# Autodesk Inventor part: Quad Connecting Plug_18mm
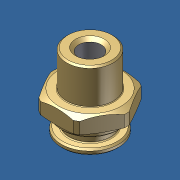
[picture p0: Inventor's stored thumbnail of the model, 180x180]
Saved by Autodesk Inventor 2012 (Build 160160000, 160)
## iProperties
Created: 2013-10
Part Number: Quad Connecting Plug_18mm
Material: Default
Document SubType Name: Modeling
Designer: Admin
Density: 1 g/cm^3
Author: Admin
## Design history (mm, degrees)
node "Quad Connecting Plug_18mm1"
node "Base1"
body "Solid1"
